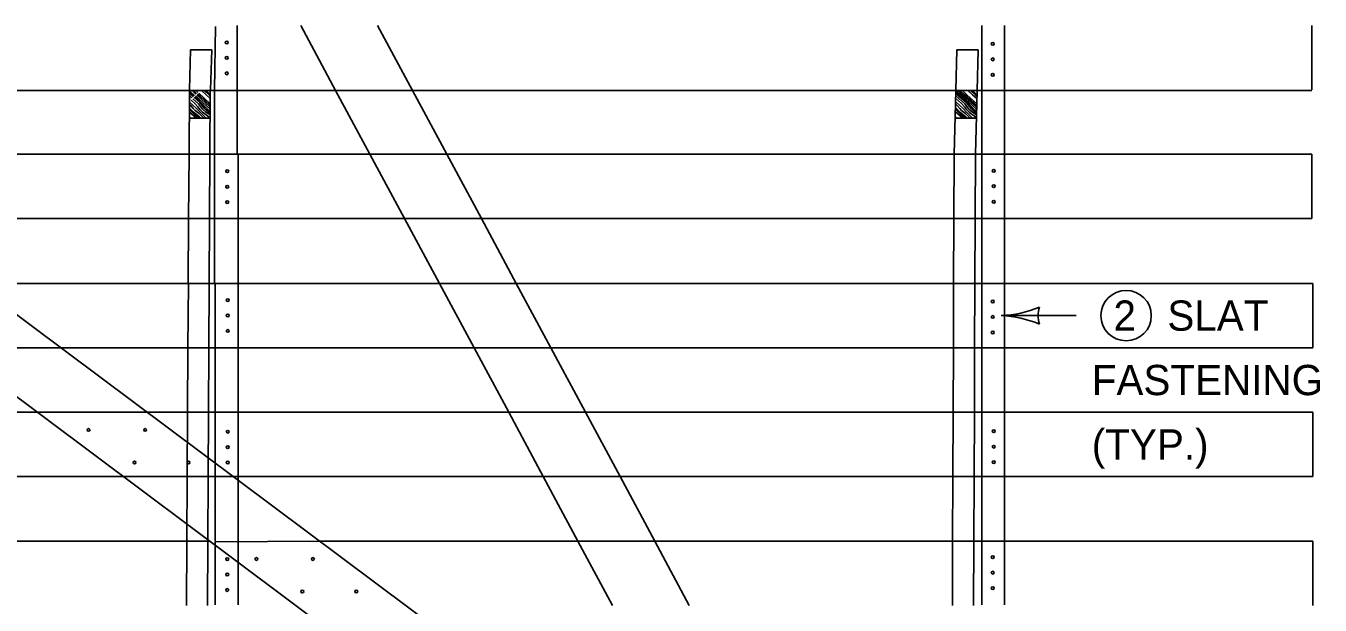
# Model space of a CAD drawing. Extents: x 49991.4 to 50021, y 49987.6 to 50011.4.
# Drawn here: x 50002.489 to 50005.058, y 49995.949 to 49997.098 of the extents above; entities that cross this region are included whole.
import ezdxf

# ---------------------------------------------------------------- set-up
doc = ezdxf.new("R2010")
doc.units = 0
for name, color, linetype in [('Level 1', 7, 'Continuous'), ('Level 2', 7, 'Continuous'), ('Level 3', 7, 'Continuous'), ('Level 4', 7, 'Continuous')]:
    doc.layers.add(name, color=color, linetype=linetype)

msp = doc.modelspace()

# ---------------------------------------------------------------- linework, layer by layer
at = {"layer": 'Level 1'}
for p, q in [((50004.8448, 49994.752), (50001.0146, 49997.6127)), ((50004.7604, 49994.652), (50000.9301, 49997.5128)), ((50005.041, 49997.099), (50005.041, 49996.9713)), ((50001.8753, 49996.97), (50005.041, 49996.97)), ((50002.8129, 49996.8435), (50002.8136, 49996.9713)), ((50002.854, 49996.8435), (50002.8547, 49996.97)), ((50002.8632, 49996.8435), (50002.8632, 49996.9713)), ((50002.9084, 49996.9713), (50002.9084, 49996.8435)), ((50003.172, 49996.8435), (50003.1038, 49996.97)), ((50003.3242, 49996.8435), (50003.2562, 49996.97)), ((50004.3347, 49996.97), (50004.3312, 49996.8435)), ((50004.3734, 49996.8435), (50004.3769, 49996.97)), ((50004.386, 49996.8435), (50004.386, 49996.97)), ((50004.4313, 49996.97), (50004.4313, 49996.8435)), ((50002.8134, 49996.915), (50002.8544, 49996.915)), ((50004.3331, 49996.915), (50004.3754, 49996.915)), ((50002.0446, 49996.8435), (50005.041, 49996.8435)), ((50005.041, 49996.8435), (50005.041, 49996.7157)), ((50002.2158, 49996.7157), (50005.041, 49996.7157)), ((50002.8113, 49996.587), (50002.8121, 49996.7157)), ((50002.8527, 49996.587), (50002.8533, 49996.7157)), ((50002.8632, 49996.587), (50002.8632, 49996.7157)), ((50002.9103, 49996.587), (50002.9103, 49996.7157)), ((50003.3098, 49996.587), (50003.2406, 49996.7157)), ((50003.4621, 49996.587), (50003.393, 49996.7157)), ((50004.3303, 49996.587), (50004.3308, 49996.7157)), ((50004.3724, 49996.587), (50004.3729, 49996.7157)), ((50004.386, 49996.587), (50004.386, 49996.7157)), ((50004.4313, 49996.7157), (50004.4313, 49996.587)), ((50002.3879, 49996.587), (50005.0428, 49996.587)), ((50005.0428, 49996.587), (50005.0428, 49996.4592)), ((50002.559, 49996.4592), (50005.0428, 49996.4592)), ((50002.8099, 49996.3316), (50002.8107, 49996.4592)), ((50002.8514, 49996.3316), (50002.852, 49996.4592)), ((50002.865, 49996.3316), (50002.865, 49996.4592)), ((50002.9103, 49996.3316), (50002.9103, 49996.4592)), ((50003.4473, 49996.3316), (50003.3785, 49996.4592)), ((50003.5995, 49996.3316), (50003.5309, 49996.4592)), ((50004.3292, 49996.3316), (50004.3297, 49996.4592)), ((50004.3715, 49996.3316), (50004.372, 49996.4592)), ((50004.386, 49996.3316), (50004.386, 49996.4592)), ((50004.4313, 49996.4592), (50004.4313, 49996.3316)), ((50000.6947, 49996.3316), (50002.5117, 49996.3316)), ((50002.7301, 49996.3316), (50003.1912, 49996.3316)), ((50003.1912, 49996.3316), (50005.0428, 49996.3316)), ((50005.0428, 49996.3316), (50005.0428, 49996.2038)), ((50000.6947, 49996.2038), (50002.6826, 49996.2038)), ((50002.8084, 49996.076), (50002.8091, 49996.2038)), ((50002.8501, 49996.076), (50002.8507, 49996.2038)), ((50002.865, 49996.076), (50002.865, 49996.2038)), ((50002.9012, 49996.2038), (50005.0428, 49996.2038)), ((50002.9103, 49996.2038), (50002.9103, 49996.076)), ((50003.5848, 49996.076), (50003.5159, 49996.2038)), ((50003.7371, 49996.076), (50003.6683, 49996.2038)), ((50004.3283, 49996.076), (50004.3288, 49996.2038)), ((50004.3706, 49996.076), (50004.371, 49996.2038)), ((50004.386, 49996.076), (50004.386, 49996.2038)), ((50004.4313, 49996.2038), (50004.4313, 49996.076)), ((50000.6947, 49996.076), (50002.8537, 49996.076)), ((50003.0722, 49996.076), (50003.8074, 49996.076)), ((50003.6912, 49996.076), (50005.0428, 49996.076)), ((50005.0428, 49996.076), (50005.0428, 49995.9482))]:
    msp.add_line(p, q, dxfattribs=at)
for points in [[(50002.8134, 49996.9647), (50002.8212, 49996.9575)], [(50002.8136, 49996.9698), (50002.816, 49996.9673), (50002.8238, 49996.96)], [(50002.8225, 49996.9587), (50002.8136, 49996.967)], [(50002.8136, 49996.9597), (50002.8185, 49996.9549)], [(50002.8189, 49996.9701), (50002.8266, 49996.9625)], [(50002.8218, 49996.9701), (50002.8278, 49996.9638)], [(50002.8228, 49996.956), (50002.8341, 49996.9462), (50002.8445, 49996.9335), (50002.8546, 49996.925)], [(50002.8548, 49996.9278), (50002.8481, 49996.9341), (50002.8353, 49996.9474), (50002.8241, 49996.9572)], [(50002.8255, 49996.9584), (50002.8328, 49996.9523), (50002.8402, 49996.9461), (50002.854, 49996.9332), (50002.8548, 49996.9323)], [(50002.8303, 49996.9661), (50002.8264, 49996.9699)], [(50002.8281, 49996.9609), (50002.8544, 49996.9373), (50002.8549, 49996.9366)], [(50002.8294, 49996.9622), (50002.8355, 49996.9578), (50002.8436, 49996.9509), (50002.855, 49996.94)], [(50002.855, 49996.9434), (50002.8429, 49996.9546), (50002.832, 49996.9646)], [(50002.8544, 49996.9545), (50002.8466, 49996.9613), (50002.8375, 49996.9698)], [(50002.8547, 49996.9585), (50002.8492, 49996.9643), (50002.8428, 49996.9701)], [(50002.8545, 49996.9617), (50002.8488, 49996.9677), (50002.846, 49996.97)], [(50002.8548, 49996.9685), (50002.8535, 49996.97)], [(50004.3756, 49996.9217), (50004.3712, 49996.9245), (50004.3674, 49996.9267), (50004.3607, 49996.933), (50004.3524, 49996.9436), (50004.3344, 49996.9594)], [(50004.3759, 49996.9323), (50004.375, 49996.9332), (50004.3613, 49996.9461), (50004.3538, 49996.9523), (50004.3345, 49996.9685)], [(50004.3758, 49996.9278), (50004.3691, 49996.9341), (50004.3563, 49996.9474), (50004.3345, 49996.9665)], [(50004.3756, 49996.925), (50004.3655, 49996.9335), (50004.3551, 49996.9462), (50004.3349, 49996.9639)], [(50004.3759, 49996.9366), (50004.3754, 49996.9373), (50004.3389, 49996.9701)], [(50004.376, 49996.94), (50004.3646, 49996.9509), (50004.3565, 49996.9578), (50004.3405, 49996.9695)], [(50004.3762, 49996.9434), (50004.3639, 49996.9546), (50004.3473, 49996.9698)], [(50004.3764, 49996.9538), (50004.3674, 49996.9613), (50004.3585, 49996.9698)], [(50004.3765, 49996.9577), (50004.3702, 49996.9643), (50004.3638, 49996.97)], [(50004.3767, 49996.9607), (50004.3698, 49996.9677), (50004.367, 49996.9701)], [(50004.3768, 49996.9672), (50004.3746, 49996.9698)], [(50002.8324, 49996.915), (50002.8318, 49996.9159), (50002.8223, 49996.9235), (50002.8143, 49996.9317), (50002.8131, 49996.9327)], [(50002.8468, 49996.915), (50002.8341, 49996.9272), (50002.8278, 49996.9341), (50002.8134, 49996.9471)], [(50002.8363, 49996.915), (50002.8334, 49996.9178), (50002.8216, 49996.9271), (50002.8141, 49996.935), (50002.8134, 49996.9356)], [(50002.842, 49996.915), (50002.8327, 49996.9244), (50002.825, 49996.9304), (50002.8214, 49996.934), (50002.8158, 49996.9409), (50002.8135, 49996.9427)], [(50002.8136, 49996.9544), (50002.8158, 49996.9525)], [(50002.8174, 49996.9509), (50002.8246, 49996.9439), (50002.8304, 49996.9374), (50002.8345, 49996.9323), (50002.8399, 49996.9267), (50002.8442, 49996.9237), (50002.8498, 49996.9196), (50002.8544, 49996.9157)], [(50002.8202, 49996.9534), (50002.8314, 49996.9436), (50002.8397, 49996.933), (50002.8463, 49996.9267), (50002.8502, 49996.9245), (50002.8545, 49996.9217)], [(50004.3534, 49996.915), (50004.3528, 49996.9159), (50004.3433, 49996.9235), (50004.3355, 49996.9317), (50004.3336, 49996.9332)], [(50004.3573, 49996.915), (50004.3544, 49996.9178), (50004.3426, 49996.9271), (50004.3351, 49996.935), (50004.3338, 49996.9361)], [(50004.3632, 49996.915), (50004.3537, 49996.9244), (50004.346, 49996.9304), (50004.3424, 49996.934), (50004.3368, 49996.9409), (50004.3339, 49996.9431)], [(50004.3754, 49996.9157), (50004.3708, 49996.9196), (50004.3652, 49996.9237), (50004.3611, 49996.9267), (50004.3555, 49996.9323), (50004.3516, 49996.9374), (50004.3456, 49996.9439), (50004.3343, 49996.9548)], [(50004.368, 49996.915), (50004.3551, 49996.9272), (50004.349, 49996.9341), (50004.3344, 49996.9471)], [(50002.8156, 49996.915), (50002.8134, 49996.9171)], [(50002.8276, 49996.915), (50002.8269, 49996.9157), (50002.8136, 49996.927)], [(50004.3332, 49996.915), (50004.3331, 49996.915)], [(50004.3368, 49996.915), (50004.3332, 49996.9182)], [(50004.3486, 49996.915), (50004.3479, 49996.9157), (50004.3335, 49996.9279)]]:
    msp.add_lwpolyline(points, dxfattribs=at)
for centre in [(50002.8877, 49997.0651), (50004.4078, 49997.0623), (50004.4078, 49997.0316), (50002.8877, 49997.0038), (50004.4078, 49997.001), (50002.8887, 49996.8096), (50004.4098, 49996.8104), (50004.4098, 49996.7798), (50002.8887, 49996.7483), (50004.4098, 49996.7491), (50002.8897, 49996.554), (50004.4078, 49996.5512), (50002.8897, 49996.5234), (50004.4078, 49996.5205), (50002.8897, 49996.4927), (50004.4078, 49996.4899), (50002.6136, 49996.2963), (50002.7257, 49996.2963), (50004.4098, 49996.2938), (50004.4098, 49996.2631), (50002.7047, 49996.2318), (50002.8118, 49996.2318), (50002.8897, 49996.2316), (50004.4098, 49996.2325), (50002.8887, 49996.0401), (50002.9466, 49996.0403), (50003.0588, 49996.0403), (50004.4078, 49996.0438), (50002.8887, 49996.0095), (50004.4078, 49996.0132), (50002.8887, 49995.9788), (50004.4078, 49995.9825), (50003.0377, 49995.9758), (50003.1448, 49995.9758)]:
    msp.add_ellipse(centre, major_axis=(0.00285, 0), ratio=0.940299, dxfattribs=at)
at = {"layer": 'Level 2'}
msp.add_circle((50004.6726, 49996.5232), 0.05, dxfattribs=at)
at = {"layer": 'Level 3'}
msp.add_line((50004.5736, 49996.5231), (50004.4247, 49996.5231), dxfattribs=at)
for centre, radius, start, end in [((50004.4132, 49996.7558), 0.233, 272.8273, 292.0772), ((50004.4155, 49996.301), 0.2223, 67.456, 87.6395), ((50004.5529, 49996.5231), 0.0548, 162.1388, 197.8612)]:
    msp.add_arc(centre, radius, start, end, dxfattribs=at)
at = {"layer": 'Level 4'}
for p, q in [((50002.8632, 49996.9713), (50002.8654, 49997.0969)), ((50002.9084, 49996.9713), (50002.9084, 49997.099)), ((50003.0346, 49997.099), (50003.1038, 49996.97)), ((50003.1868, 49997.099), (50003.2562, 49996.97)), ((50004.386, 49996.97), (50004.386, 49997.099)), ((50004.4313, 49997.099), (50004.4313, 49996.97)), ((50002.8136, 49996.9713), (50002.8156, 49997.0505)), ((50002.8156, 49997.0505), (50002.8579, 49997.0505)), ((50002.8558, 49996.9713), (50002.8579, 49997.0505)), ((50004.3347, 49996.97), (50004.3368, 49997.0505)), ((50004.3368, 49997.0505), (50004.379, 49997.0505)), ((50004.3769, 49996.97), (50004.379, 49997.0505)), ((50002.8121, 49996.7157), (50002.8129, 49996.8435)), ((50002.8533, 49996.7157), (50002.854, 49996.8435)), ((50002.8632, 49996.7157), (50002.8632, 49996.8435)), ((50002.9103, 49996.7157), (50002.9103, 49996.8435)), ((50003.172, 49996.8435), (50003.2406, 49996.7157)), ((50003.3242, 49996.8435), (50003.393, 49996.7157)), ((50004.3306, 49996.7157), (50004.3313, 49996.8435)), ((50004.373, 49996.7157), (50004.3734, 49996.8435)), ((50004.386, 49996.7157), (50004.386, 49996.8435)), ((50004.4313, 49996.8435), (50004.4313, 49996.7157)), ((50002.8107, 49996.4592), (50002.8115, 49996.587)), ((50002.8522, 49996.4592), (50002.8527, 49996.587)), ((50002.865, 49996.4592), (50002.865, 49996.587)), ((50002.9103, 49996.4592), (50002.9103, 49996.587)), ((50003.3098, 49996.587), (50003.3785, 49996.4592)), ((50003.4621, 49996.587), (50003.5309, 49996.4592)), ((50004.3297, 49996.4592), (50004.3303, 49996.587)), ((50004.372, 49996.4592), (50004.3725, 49996.587)), ((50004.386, 49996.4592), (50004.386, 49996.587)), ((50004.4313, 49996.587), (50004.4313, 49996.4592)), ((50002.3406, 49996.4592), (50002.559, 49996.4592)), ((50002.5117, 49996.3316), (50002.7301, 49996.3316)), ((50002.8091, 49996.2038), (50002.8099, 49996.3316)), ((50002.8509, 49996.2038), (50002.8514, 49996.3316)), ((50002.865, 49996.2048), (50002.865, 49996.3312)), ((50002.9103, 49996.3312), (50002.9103, 49996.2059)), ((50003.4473, 49996.3316), (50003.5159, 49996.2038)), ((50003.5995, 49996.3316), (50003.6683, 49996.2038)), ((50004.3288, 49996.2038), (50004.3294, 49996.3316)), ((50004.3711, 49996.2038), (50004.3715, 49996.3316)), ((50004.386, 49996.2048), (50004.386, 49996.3316)), ((50004.4313, 49996.3316), (50004.4313, 49996.2059)), ((50002.6826, 49996.2038), (50002.9012, 49996.2038)), ((50002.8076, 49995.9482), (50002.8084, 49996.076)), ((50002.8494, 49995.9482), (50002.8501, 49996.076)), ((50002.865, 49996.0741), (50003.0722, 49996.076)), ((50002.865, 49995.9495), (50002.865, 49996.0741)), ((50002.9103, 49996.0751), (50002.9103, 49995.9495)), ((50003.5848, 49996.076), (50003.6535, 49995.9482)), ((50003.7371, 49996.076), (50003.8057, 49995.9482)), ((50004.3278, 49995.9482), (50004.3283, 49996.076)), ((50004.37, 49995.9482), (50004.3706, 49996.076)), ((50004.386, 49995.9495), (50004.386, 49996.0741)), ((50004.4313, 49996.0751), (50004.4313, 49995.9495))]:
    msp.add_line(p, q, dxfattribs=at)
for centre in [(50002.8877, 49997.0345), (50002.8887, 49996.7789), (50002.8897, 49996.2929), (50002.8897, 49996.2622)]:
    msp.add_ellipse(centre, major_axis=(0.00285, 0), ratio=0.940299, dxfattribs=at)

# ---------------------------------------------------------------- texts
at = {"layer": 'Level 2'}
for s, p in [('2', (50004.6475, 49996.4932)), ('SLAT', (50004.7544, 49996.4932)), ('FASTENING', (50004.6044, 49996.3654)), ('(TYP.)', (50004.6044, 49996.2376))]:
    msp.add_text(s, height=0.06, dxfattribs=at).set_placement(p)

doc.saveas('drawing.dxf')
